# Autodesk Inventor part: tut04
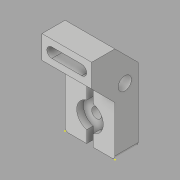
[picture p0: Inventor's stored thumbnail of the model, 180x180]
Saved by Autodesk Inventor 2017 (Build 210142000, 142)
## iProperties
Created: 2015-03
Part Number: tut04
Material: Generic
Document SubType Name: Modeling
Designer: Sandeep
Density: 1 g/cm^3
Appearance: Default
Author: Sandeep
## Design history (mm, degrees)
sketch "Sketch1"
  geometry: L1 (0, 0)-(0, 30); L2 (0, 30)-(-14, 44); L3 (-14, 44)-(-14, 58); L4 (-14, 58)-(0, 58); L5 (14, 44)-(14, 0); L6 (14, 0)-(0, 0); L7 (0, 58)-(14, 44)
  constraints: 14 end point, 3 parallel, 1 horizontal, 1 perpendicular, 1 vertical
  dimensions: "d0" = 14 distance between parallel lines of L5 L1; "d1" = 14 distance from line of L4.end L5; "d2" = 14 horizontal distance of L4.end L5.start; "d3" = 28 distance between parallel lines of L3 L5; "d4" = 58 distance between parallel lines of L4 L6; "d5" = 14 distance of L2.end L3.end
extrude "Extrusion1" new body sketch "Sketch1" distance "d6" = 30; taper "d7" = 0 deg
sketch "Sketch2"
  geometry: 1 further point
hole "Hole1" diameter "d10" = 8; stored, may be unused: countersink angle "d14" = 90 deg, drill point angle "d16" = 118 deg; dims "d8" = 21, "d9" = 8, "d11" = 6, "d12" = 4, "d13" = 2, "d15" = 8
sketch "Sketch3"
  geometry: L1 (0, 0)-(30, 0) reference; L2 (0, -30)-(30, -30) reference; L3 (30, 0)-(30, -30) reference; L4 (13, 0)-(13, -7.254); L5 (0, 3)-(30, 3) reference; L6 (17, 0)-(17, -7.254); L7 (15, -15)-(15, 7.075); L8 (13, 0)-(17, 0); L9 (-6.754, -15)-(33.848, -15); L10 (13, -22.746)-(13, -30); L11 (17, -30)-(17, -22.746); C1 r 3 at (15, -15); A1 r 8 centre (15, -15) between (13, -7.254) and (13, -22.746); A2 r 8 centre (15, -15) between (17, -22.746) and (17, -7.254)
  constraints: 14 end point, 5 point on line, 4 point on circle, 3 centre point, 2 parallel, 2 perpendicular, 1 coincident, 1 collinear, 1 horizontal, 1 vertical, 2 other
  dimensions: "d19" = 6 diameter of C1; "d21" = 15 distance from line of L2 A1.centre; "d22" = 15 distance from line of A1.centre L3; "d23" = 4 distance between parallel lines of L6 L4; "d24" = 4 distance between parallel lines of L11 L10; "d25" = 8 radius of A2; "d26" = 8 radius of A1
sketch "Sketch4"
  geometry: 1 further point
extrude "Extrusion2" cut sketch "Sketch3" distance "d27" = 4; taper "d28" = 0 deg
sketch "Sketch5"
  geometry: L1 (6, 7)-(24, 7); L2 (6, 4)-(24, 4); L3 (24, 10)-(6, 10); L4 (0, 14)-(30, 14) reference; L5 (30, 0)-(30, 14) reference; A1 r 3 centre (6, 7) between (6, 10) and (6, 4); A2 r 3 centre (24, 7) between (24, 4) and (24, 10); 2 further points
  constraints: 8 end point, 4 point on circle, 4 tangent, 2 centre point, 1 horizontal, 1 midpoint, 1 parallel
  dimensions: "d29" = 7 distance between parallel lines of L4 L1; "d30" = 18 distance of L1.start L1.end; "d31" = 6 distance from line of L5 L1.end; "d32" = 3 radius of A2
extrude "Extrusion3" cut sketch "Sketch5" distance "d33" = 11; taper "d34" = 0 deg
sketch "Sketch6"
  geometry: C1 r 3 at (0, 0); C2 r 3 at (0, 0) reference; 1 further point
  constraints: 1 centre point, 1 concentric
extrude "Extrusion4" cut sketch "Sketch6" distance "d35" = 35.25; taper "d36" = 0 deg
fillet "Fillet2" dims "d37" = 2
body "Solid1"
other parameters: "d20" = 16
